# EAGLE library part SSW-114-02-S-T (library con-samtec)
THROUGH-HOLE .025" SQ POST SOCKET Source: Samtec SSW.pdf
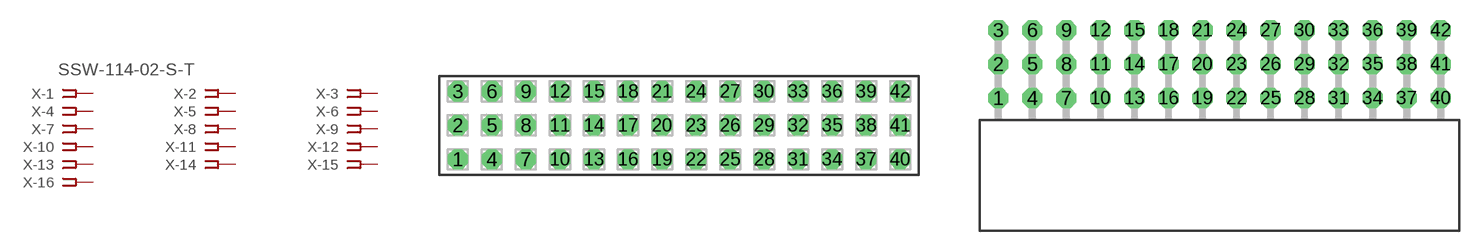
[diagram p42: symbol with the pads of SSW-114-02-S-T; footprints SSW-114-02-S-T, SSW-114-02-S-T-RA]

Designator prefix X; gates -1=FPINV -2=FPIN -3=FPIN -4=FPIN -5=FPIN -6=FPIN -7=FPIN -8=FPIN -9=FPIN -10=FPIN -11=FPIN -12=FPIN -13=FPIN -14=FPIN -15=FPIN -16=FPIN -17=FPIN -18=FPIN -19=FPIN -20=FPIN -21=FPIN -22=FPIN -23=FPIN -24=FPIN -25=FPIN -26=FPIN -27=FPIN -28=FPIN -29=FPIN -30=FPIN -31=FPIN -32=FPIN -33=FPIN -34=FPIN -35=FPIN -36=FPIN -37=FPIN -38=FPIN -39=FPIN -40=FPIN -41=FPIN -42=FPIN

## SSW-114-02-S-T (MPN: SSW-114-02-S-T; OC_FARNELL: unknown; OC_NEWARK: 82P6536)  [SSW-114-02-S-T]
1  -1:1  pas
2  -2:1  pas
3  -3:1  pas
4  -4:1  pas
5  -5:1  pas
6  -6:1  pas
7  -7:1  pas
8  -8:1  pas
9  -9:1  pas
10  -10:1  pas
11  -11:1  pas
12  -12:1  pas
13  -13:1  pas
14  -14:1  pas
15  -15:1  pas
16  -16:1  pas
17  -17:1  pas
18  -18:1  pas
19  -19:1  pas
20  -20:1  pas
21  -21:1  pas
22  -22:1  pas
23  -23:1  pas
24  -24:1  pas
25  -25:1  pas
26  -26:1  pas
27  -27:1  pas
28  -28:1  pas
29  -29:1  pas
30  -30:1  pas
31  -31:1  pas
32  -32:1  pas
33  -33:1  pas
34  -34:1  pas
35  -35:1  pas
36  -36:1  pas
37  -37:1  pas
38  -38:1  pas
39  -39:1  pas
40  -40:1  pas
41  -41:1  pas
42  -42:1  pas

## SSW-114-02-S-TRA (MPN: SSW-114-02-S-T-RA; OC_FARNELL: unknown; OC_NEWARK: 82P6538)  [SSW-114-02-S-T-RA]
Pads as for SSW-114-02-S-T

## Footprint SSW-114-02-S-T (pad centres in mm)
THROUGH-HOLE .025" SQ POST SOCKET Source: Samtec SSW.pdf
drill 1 pad 1.5 octagon: 1 -16.51,-2.54; 2 -16.51,0; 3 -16.51,2.54; 4 -13.97,-2.54; 5 -13.97,0; 6 -13.97,2.54; 7 -11.43,-2.54; 8 -11.43,0; 9 -11.43,2.54; 10 -8.89,-2.54; 11 -8.89,0; 12 -8.89,2.54; 13 -6.35,-2.54; 14 -6.35,0; 15 -6.35,2.54; 16 -3.81,-2.54; 17 -3.81,0; 18 -3.81,2.54; 19 -1.27,-2.54; 20 -1.27,0; 21 -1.27,2.54; 22 1.27,-2.54; 23 1.27,0; 24 1.27,2.54; 25 3.81,-2.54; 26 3.81,0; 27 3.81,2.54; 28 6.35,-2.54; 29 6.35,0; 30 6.35,2.54; 31 8.89,-2.54; 32 8.89,0; 33 8.89,2.54; 34 11.43,-2.54; 35 11.43,0; 36 11.43,2.54; 37 13.97,-2.54; 38 13.97,0; 39 13.97,2.54; 40 16.51,-2.54; 41 16.51,0; 42 16.51,2.54

## Footprint SSW-114-02-S-T-RA (pad centres in mm)
THROUGH-HOLE .025" SQ POST SOCKET Source: Samtec SSW.pdf
drill 1 pad 1.5 octagon: 1 -16.51,1.524; 2 -16.51,4.064; 3 -16.51,6.604; 4 -13.97,1.524; 5 -13.97,4.064; 6 -13.97,6.604; 7 -11.43,1.524; 8 -11.43,4.064; 9 -11.43,6.604; 10 -8.89,1.524; 11 -8.89,4.064; 12 -8.89,6.604; 13 -6.35,1.524; 14 -6.35,4.064; 15 -6.35,6.604; 16 -3.81,1.524; 17 -3.81,4.064; 18 -3.81,6.604; 19 -1.27,1.524; 20 -1.27,4.064; 21 -1.27,6.604; 22 1.27,1.524; 23 1.27,4.064; 24 1.27,6.604; 25 3.81,1.524; 26 3.81,4.064; 27 3.81,6.604; 28 6.35,1.524; 29 6.35,4.064; 30 6.35,6.604; 31 8.89,1.524; 32 8.89,4.064; 33 8.89,6.604; 34 11.43,1.524; 35 11.43,4.064; 36 11.43,6.604; 37 13.97,1.524; 38 13.97,4.064; 39 13.97,6.604; 40 16.51,1.524; 41 16.51,4.064; 42 16.51,6.604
